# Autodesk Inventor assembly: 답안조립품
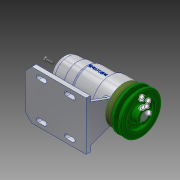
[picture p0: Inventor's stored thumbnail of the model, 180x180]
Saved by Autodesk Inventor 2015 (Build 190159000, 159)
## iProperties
Created: 2017-09
Part Number: 답안조립품
Document SubType Name: Assembly
Designer: owner
Author: owner
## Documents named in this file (12)
- C:\Users\owner\Desktop\470907V1003\답안조립품.iam
- C:\Users\owner\Desktop\470907V1003\본체.ipt
- C:\Users\owner\Desktop\470907V1003\커버.ipt
- C:\Users\owner\Desktop\470907V1003\볼트 M4 x 12.ipt
- C:\Users\owner\Desktop\470907V1003\오일 실 20x35x7.ipt
- C:\Users\owner\Desktop\470907V1003\베어링 6004.ipt
- C:\Users\owner\Desktop\470907V1003\축.ipt
- C:\Users\owner\Desktop\470907V1003\베어링 51202.ipt
- C:\Users\owner\Desktop\470907V1003\어댑터슬리브.ipt
- C:\Users\owner\Desktop\470907V1003\V벨트풀리.ipt
- C:\Users\owner\Desktop\470907V1003\멈춤나사 M3x8.ipt
- C:\Users\owner\Desktop\470907V1003\키 5 x 5 x 16.ipt
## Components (1 placed, 1 different names)
1. V벨트풀리:1
